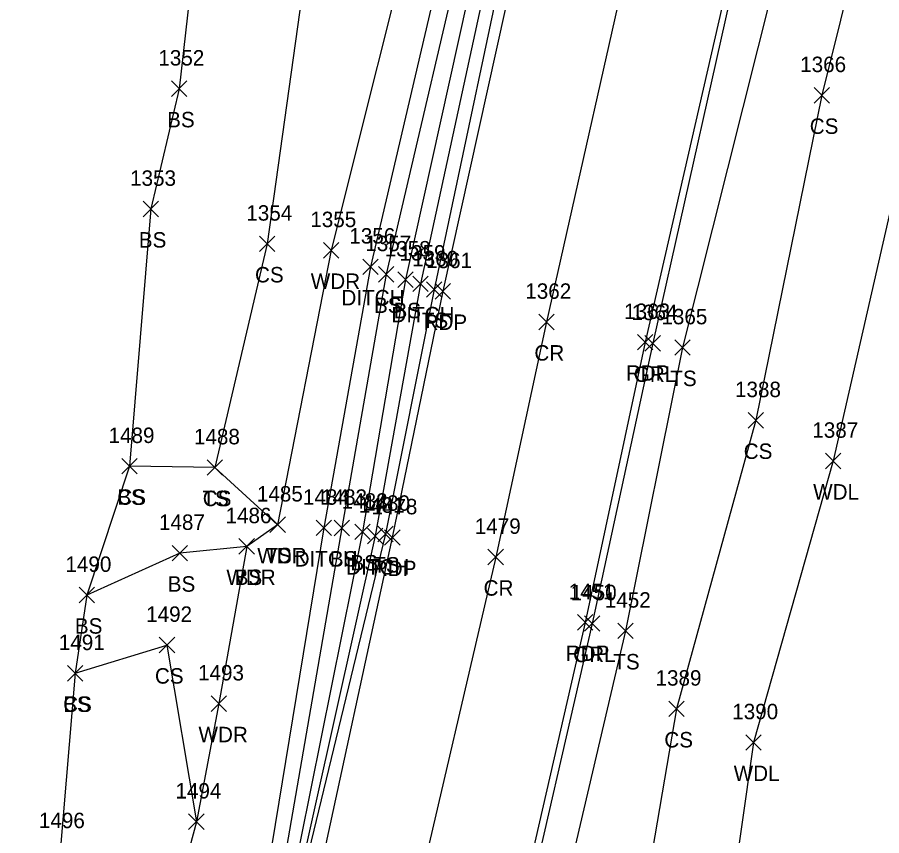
# Model space of a CAD drawing. Extents: x 1551995 to 1555700, y 777276 to 783130.
# Drawn here: x 1554796.1 to 1554908, y 777703.8 to 777809.8 of the extents above; entities that cross this region are included whole.
import ezdxf

# ---------------------------------------------------------------- set-up
doc = ezdxf.new("R2010")
doc.units = 0
for name, color, linetype in [('D_A', 7, 'Continuous'), ('D_I', 7, 'Continuous'), ('D_TIC', 7, 'Continuous'), ('DD', 7, 'Continuous'), ('L_A', 7, 'Continuous'), ('L_I', 7, 'Continuous'), ('L_TIC', 7, 'Continuous'), ('LAWA', 7, 'Continuous'), ('LELB', 7, 'Continuous'), ('P_A', 7, 'Continuous'), ('P_I', 7, 'Continuous'), ('P_TIC', 7, 'Continuous'), ('PET', 7, 'Continuous'), ('PRC', 7, 'Continuous'), ('R_A', 7, 'Continuous'), ('R_I', 7, 'Continuous'), ('R_TIC', 7, 'Continuous'), ('RGR', 7, 'Continuous')]:
    doc.layers.add(name, color=color, linetype=linetype)

msp = doc.modelspace()

# ---------------------------------------------------------------- linework, layer by layer
at = {"layer": 'D_TIC'}
for points in [[(1554840.81, 777776.5), (1554842.81, 777778.5)], [(1554842.81, 777776.5), (1554840.81, 777778.5)], [(1554847.28, 777774.3), (1554849.28, 777776.3)], [(1554849.28, 777774.3), (1554847.28, 777776.3)], [(1554834.76, 777742.69), (1554836.76, 777744.69)], [(1554836.76, 777742.69), (1554834.76, 777744.69)], [(1554841.42, 777741.65), (1554843.42, 777743.65)], [(1554843.42, 777741.65), (1554841.42, 777743.65)]]:
    msp.add_lwpolyline(points, dxfattribs=at)
at = {"layer": 'DD'}
for points in [[(1554922.06, 778109.96), (1554923.19, 778109.15), (1554925.69, 778108.05), (1554928.67, 778106.77), (1554922.03, 778089.94), (1554922.01, 778087.44), (1554918.96, 778075.67), (1554907.32, 778037.79), (1554897.01, 777996.11), (1554888.71, 777961.75), (1554879.52, 777917.82), (1554870.92, 777875.83), (1554859.53, 777827.03), (1554848.28, 777775.3), (1554842.42, 777742.65), (1554832.08, 777696.16), (1554826.68, 777674.46), (1554825.9, 777662.94)], [(1554853.39, 777826.98), (1554841.81, 777777.5), (1554835.76, 777743.69), (1554828.13, 777697.14), (1554822.33, 777678.76), (1554820.5, 777673.08), (1554821.28, 777667.69), (1554820.54, 777665.87), (1554819.99, 777658.61), (1554821.52, 777659.17), (1554812.27, 777628.19), (1554798.58, 777600.46), (1554777.91, 777552.75), (1554765.73, 777525.09), (1554749.72, 777489.17), (1554733.83, 777456.87), (1554735, 777456.04), (1554736.9, 777455.11), (1554739.85, 777453.59)]]:
    msp.add_lwpolyline(points, dxfattribs=at)
at = {"layer": 'L_TIC'}
for points in [[(1554816.04, 777799.55), (1554818.04, 777801.55)], [(1554818.04, 777799.55), (1554816.04, 777801.55)], [(1554899.26, 777798.7), (1554901.26, 777800.7)], [(1554901.26, 777798.7), (1554899.26, 777800.7)], [(1554812.37, 777783.98), (1554814.37, 777785.98)], [(1554814.37, 777783.98), (1554812.37, 777785.98)], [(1554827.42, 777779.47), (1554829.42, 777781.47)], [(1554829.42, 777779.47), (1554827.42, 777781.47)], [(1554835.72, 777778.63), (1554837.72, 777780.63)], [(1554837.72, 777778.63), (1554835.72, 777780.63)], [(1554842.83, 777775.52), (1554844.83, 777777.52)], [(1554844.83, 777775.52), (1554842.83, 777777.52)], [(1554845.36, 777774.83), (1554847.36, 777776.83)], [(1554847.36, 777774.83), (1554845.36, 777776.83)], [(1554849.05, 777773.56), (1554851.05, 777775.56)], [(1554851.05, 777773.56), (1554849.05, 777775.56)], [(1554881.23, 777766.05), (1554883.23, 777768.05)], [(1554883.23, 777766.05), (1554881.23, 777768.05)], [(1554890.71, 777756.62), (1554892.71, 777758.62)], [(1554892.71, 777756.62), (1554890.71, 777758.62)], [(1554900.73, 777751.36), (1554902.73, 777753.36)], [(1554902.73, 777751.36), (1554900.73, 777753.36)], [(1554809.59, 777750.68), (1554811.59, 777752.68)], [(1554811.59, 777750.68), (1554809.59, 777752.68)], [(1554809.59, 777750.68), (1554811.59, 777752.68)], [(1554811.59, 777750.68), (1554809.59, 777752.68)], [(1554820.65, 777750.51), (1554822.65, 777752.51)], [(1554822.65, 777750.51), (1554820.65, 777752.51)], [(1554820.65, 777750.51), (1554822.65, 777752.51)], [(1554822.65, 777750.51), (1554820.65, 777752.51)], [(1554828.79, 777743.11), (1554830.79, 777745.11)], [(1554830.79, 777743.11), (1554828.79, 777745.11)], [(1554828.79, 777743.11), (1554830.79, 777745.11)], [(1554830.79, 777743.11), (1554828.79, 777745.11)], [(1554837.11, 777742.68), (1554839.11, 777744.68)], [(1554839.11, 777742.68), (1554837.11, 777744.68)], [(1554839.77, 777742.18), (1554841.77, 777744.18)], [(1554841.77, 777742.18), (1554839.77, 777744.18)], [(1554842.76, 777741.91), (1554844.76, 777743.91)], [(1554844.76, 777741.91), (1554842.76, 777743.91)], [(1554824.78, 777740.3), (1554826.78, 777742.3)], [(1554826.78, 777740.3), (1554824.78, 777742.3)], [(1554824.78, 777740.3), (1554826.78, 777742.3)], [(1554826.78, 777740.3), (1554824.78, 777742.3)], [(1554816.12, 777739.43), (1554818.12, 777741.43)], [(1554818.12, 777739.43), (1554816.12, 777741.43)], [(1554804.09, 777734), (1554806.09, 777736)], [(1554806.09, 777734), (1554804.09, 777736)], [(1554804.09, 777734), (1554806.09, 777736)], [(1554806.09, 777734), (1554804.09, 777736)], [(1554873.85, 777729.37), (1554875.85, 777731.37)], [(1554875.85, 777729.37), (1554873.85, 777731.37)], [(1554814.46, 777727.53), (1554816.46, 777729.53)], [(1554816.46, 777727.53), (1554814.46, 777729.53)], [(1554802.57, 777723.87), (1554804.57, 777725.87)], [(1554804.57, 777723.87), (1554802.57, 777725.87)], [(1554802.57, 777723.87), (1554804.57, 777725.87)], [(1554804.57, 777723.87), (1554802.57, 777725.87)], [(1554821.18, 777719.94), (1554823.18, 777721.94)], [(1554823.18, 777719.94), (1554821.18, 777721.94)], [(1554880.43, 777719.27), (1554882.43, 777721.27)], [(1554882.43, 777719.27), (1554880.43, 777721.27)], [(1554890.43, 777714.92), (1554892.43, 777716.92)], [(1554892.43, 777714.92), (1554890.43, 777716.92)], [(1554818.26, 777704.66), (1554820.26, 777706.66)], [(1554820.26, 777704.66), (1554818.26, 777706.66)], [(1554818.26, 777704.66), (1554820.26, 777706.66)], [(1554820.26, 777704.66), (1554818.26, 777706.66)]]:
    msp.add_lwpolyline(points, dxfattribs=at)
at = {"layer": 'LAWA'}
for points in [[(1554924.17, 777845.95), (1554911.99, 777797.39), (1554901.73, 777752.36), (1554891.43, 777715.92), (1554886.53, 777681.63), (1554885.54, 777676.35), (1554886.43, 777672.72), (1554885.1, 777668.28), (1554876.24, 777640.92), (1554874.65, 777639.02), (1554865.05, 777604.93), (1554832.26, 777556.58), (1554828.6, 777545), (1554825.77, 777534.55), (1554825.26, 777531.03), (1554824.11, 777527.47), (1554817.13, 777514.36), (1554810.78, 777500.84), (1554797.7, 777469.38), (1554813.54, 777462.7)], [(1554848.67, 777827.4), (1554836.72, 777779.63), (1554829.79, 777744.11), (1554825.78, 777741.3), (1554822.18, 777720.94), (1554819.26, 777705.66), (1554810.77, 777674.16), (1554804.68, 777658.7), (1554794.95, 777639.81), (1554796.98, 777635.44), (1554794.4, 777626.38), (1554790.25, 777608.46), (1554781.8, 777582.48), (1554770.39, 777556.32), (1554759.95, 777527.2), (1554742.53, 777489.58), (1554728.19, 777462.54)]]:
    msp.add_lwpolyline(points, dxfattribs=at)
at = {"layer": 'LELB'}
for points in [[(1554956.78, 778082.85), (1554952.54, 778067.25), (1554941.7, 778025.45), (1554932.23, 777987.42), (1554924.92, 777953.42), (1554914.28, 777909.64), (1554906.04, 777867.54), (1554895.88, 777821.34), (1554882.23, 777767.05), (1554874.85, 777730.37), (1554865.16, 777689.06), (1554854.06, 777643.96), (1554841.07, 777598.56), (1554825.8, 777560.58)], [(1554954.84, 778026.93), (1554940.94, 777981.64), (1554932.87, 777954.14), (1554929.76, 777924.84), (1554918.75, 777893.91), (1554912.39, 777848.48), (1554900.26, 777799.7), (1554891.71, 777757.62), (1554881.43, 777720.27), (1554874.58, 777680.06), (1554873.83, 777672.65), (1554864.12, 777644.24), (1554854.56, 777607.14), (1554832.26, 777556.58)], [(1554818.74, 777989.99), (1554826.95, 777965.67), (1554828.21, 777938.79), (1554827.61, 777892.43), (1554825.56, 777859.47), (1554820.31, 777829.58), (1554817.04, 777800.55), (1554813.37, 777784.98), (1554810.59, 777751.68), (1554805.09, 777735), (1554803.57, 777724.87), (1554801.62, 777701.82), (1554799.08, 777679.52), (1554798, 777658.89), (1554794.95, 777639.81), (1554778.13, 777607.5), (1554759.36, 777559.57), (1554752.31, 777545.79)], [(1554828.62, 777989.99), (1554839.45, 777979.91), (1554836.31, 777967.58), (1554843.93, 777927.48), (1554845.21, 777880.49), (1554844.2, 777852.94), (1554834.62, 777824.64), (1554828.42, 777780.47), (1554821.65, 777751.51), (1554810.59, 777751.68)], [(1554870.92, 777875.83), (1554861.08, 777826.54), (1554850.05, 777774.56), (1554843.76, 777742.91), (1554832.54, 777696.52), (1554826.68, 777674.46)], [(1554855.73, 777827.33), (1554843.83, 777776.52), (1554838.11, 777743.68), (1554829.99, 777696.83), (1554823.99, 777679.3), (1554821.48, 777673.86), (1554821.86, 777673.52), (1554823.73, 777663.64), (1554822.4, 777659.03), (1554813.94, 777627.98), (1554800.18, 777599.92), (1554780.06, 777551.51), (1554767.45, 777524.55), (1554751.73, 777488.16), (1554735, 777456.04)], [(1554857.76, 777827.38), (1554846.36, 777775.83), (1554840.77, 777743.18), (1554831.41, 777696.67), (1554825.48, 777677.69), (1554824.51, 777673.63), (1554823.78, 777673.32), (1554824.92, 777663.42), (1554823.59, 777658.72), (1554814.97, 777627.54), (1554801.99, 777599.47), (1554782.65, 777550.32), (1554769.22, 777523.47), (1554754.18, 777487.46), (1554736.9, 777455.11)], [(1554829.79, 777744.11), (1554821.65, 777751.51)], [(1554825.78, 777741.3), (1554817.12, 777740.43), (1554805.09, 777735)], [(1554803.57, 777724.87), (1554815.46, 777728.53), (1554819.26, 777705.66)]]:
    msp.add_lwpolyline(points, dxfattribs=at)
at = {"layer": 'P_TIC'}
for points in [[(1554850.19, 777773.32), (1554852.19, 777775.32)], [(1554852.19, 777773.32), (1554850.19, 777775.32)], [(1554863.6, 777769.35), (1554865.6, 777771.35)], [(1554865.6, 777769.35), (1554863.6, 777771.35)], [(1554876.4, 777766.74), (1554878.4, 777768.74)], [(1554878.4, 777766.74), (1554876.4, 777768.74)], [(1554843.64, 777741.45), (1554845.64, 777743.45)], [(1554845.64, 777741.45), (1554843.64, 777743.45)], [(1554857.03, 777738.92), (1554859.03, 777740.92)], [(1554859.03, 777738.92), (1554857.03, 777740.92)], [(1554868.61, 777730.46), (1554870.61, 777732.46)], [(1554870.61, 777730.46), (1554868.61, 777732.46)]]:
    msp.add_lwpolyline(points, dxfattribs=at)
at = {"layer": 'PET'}
for points in [[(1554862.74, 777826.66), (1554851.19, 777774.32), (1554844.64, 777742.45), (1554834.58, 777696.01), (1554825.9, 777662.94), (1554824.47, 777658.25), (1554815.91, 777627.5), (1554805.87, 777597.98), (1554786.84, 777548.46), (1554774.55, 777520.74), (1554758.12, 777485.1), (1554742.1, 777452.42), (1554722.77, 777413.11), (1554709.98, 777388.33), (1554692.97, 777354.45), (1554662.63, 777294.3)], [(1554889.9, 777822.39), (1554877.4, 777767.74), (1554869.61, 777731.46), (1554860.02, 777689.61), (1554848.79, 777645.37), (1554834.77, 777600.99), (1554821.88, 777564.77), (1554812, 777537.71), (1554799.6, 777509.17), (1554784.62, 777476.27), (1554767.28, 777440.72), (1554755.97, 777417.1), (1554737.76, 777381.53), (1554717.46, 777342.52), (1554685.83, 777281.18)]]:
    msp.add_lwpolyline(points, dxfattribs=at)
at = {"layer": 'PRC'}
msp.add_lwpolyline([(1554876.72, 777824.26), (1554864.6, 777770.35), (1554858.03, 777739.92), (1554847.21, 777693.38), (1554836.59, 777653.01), (1554828.61, 777623.61), (1554818.04, 777593.07), (1554799.63, 777543.85), (1554787.19, 777515.25), (1554771.79, 777480.71), (1554754.78, 777446.13), (1554727.16, 777390.73), (1554704.95, 777347.63), (1554675, 777287.76)], dxfattribs=at)
at = {"layer": 'R_TIC'}
for points in [[(1554877.36, 777766.59), (1554879.36, 777768.59)], [(1554879.36, 777766.59), (1554877.36, 777768.59)], [(1554869.52, 777730.32), (1554871.52, 777732.32)], [(1554871.52, 777730.32), (1554869.52, 777732.32)]]:
    msp.add_lwpolyline(points, dxfattribs=at)
at = {"layer": 'RGR'}
msp.add_lwpolyline([(1555039.56, 778268.3), (1555013.62, 778223), (1554996.63, 778189.88), (1554979.88, 778154.08), (1554968.24, 778124.65), (1554958.2, 778096.32), (1554950.97, 778072.94), (1554937.27, 778027.95), (1554927.65, 777988.1), (1554919.66, 777954.37), (1554909.72, 777910.11), (1554900.5, 777868.18), (1554890.69, 777822.54), (1554878.36, 777767.59), (1554870.52, 777731.32), (1554860.9, 777689.38), (1554849.55, 777645.14), (1554835.81, 777600.33), (1554822.79, 777564.15), (1554817.07, 777548.72), (1554816.7, 777536.06)], dxfattribs=at)

# ---------------------------------------------------------------- texts
at = {"layer": 'D_A'}
for p in [(1554838.05, 777772.5), (1554844.52, 777770.3), (1554831.99, 777738.69), (1554838.66, 777737.65)]:
    msp.add_text('DITCH', height=2, dxfattribs=at).set_placement(p)
at = {"layer": 'D_I'}
for s, p in [('1356', (1554839.07, 777780.5)), ('1359', (1554845.58, 777778.3)), ('1484', (1554833.06, 777746.69)), ('1481', (1554840.3, 777745.65))]:
    msp.add_text(s, height=2, dxfattribs=at).set_placement(p)
at = {"layer": 'L_A'}
for s, p in [('BS', (1554815.48, 777795.55)), ('CS', (1554898.7, 777794.7)), ('BS', (1554811.81, 777779.98)), ('CS', (1554826.86, 777775.47)), ('WDR', (1554834.08, 777774.63)), ('BS', (1554842.27, 777771.52)), ('BS', (1554844.8, 777770.83)), ('TS', (1554848.46, 777769.56)), ('TS', (1554880.64, 777762.05)), ('CS', (1554890.15, 777752.62)), ('WDL', (1554899.14, 777747.36)), ('CS', (1554809.03, 777746.68)), ('BS', (1554809.03, 777746.68)), ('TS', (1554820.05, 777746.51)), ('CS', (1554820.09, 777746.51)), ('WDR', (1554827.15, 777739.11)), ('TS', (1554828.2, 777739.11)), ('BS', (1554836.55, 777738.68)), ('BS', (1554839.21, 777738.18)), ('TS', (1554842.17, 777737.91)), ('WDR', (1554823.15, 777736.3)), ('BS', (1554824.22, 777736.3)), ('BS', (1554815.56, 777735.43)), ('BS', (1554803.53, 777730)), ('BS', (1554803.53, 777730)), ('TS', (1554873.26, 777725.37)), ('CS', (1554813.9, 777723.53)), ('CS', (1554802.01, 777719.87)), ('BS', (1554802.01, 777719.87)), ('WDR', (1554819.54, 777715.94)), ('CS', (1554879.87, 777715.27)), ('WDL', (1554888.85, 777710.92))]:
    msp.add_text(s, height=2, dxfattribs=at).set_placement(p)
at = {"layer": 'L_I'}
for s, p in [('1352', (1554814.34, 777803.55)), ('1366', (1554897.46, 777802.7)), ('1353', (1554810.68, 777787.98)), ('1354', (1554825.73, 777783.47)), ('1355', (1554834.02, 777782.63)), ('1357', (1554841.14, 777779.52)), ('1358', (1554843.66, 777778.83)), ('1360', (1554847.22, 777777.56)), ('1365', (1554879.49, 777770.05)), ('1388', (1554889.02, 777760.62)), ('1387', (1554899.03, 777755.36)), ('1489', (1554807.89, 777754.68)), ('1489', (1554807.89, 777754.68)), ('1488', (1554818.95, 777754.51)), ('1488', (1554818.95, 777754.51)), ('1485', (1554827.1, 777747.11)), ('1485', (1554827.1, 777747.11)), ('1483', (1554835.42, 777746.68)), ('1482', (1554838.08, 777746.18)), ('1480', (1554840.98, 777745.91)), ('1486', (1554823.04, 777744.3)), ('1486', (1554823.04, 777744.3)), ('1487', (1554814.42, 777743.43)), ('1490', (1554802.31, 777738)), ('1490', (1554802.31, 777738)), ('1452', (1554872.16, 777733.37)), ('1492', (1554812.76, 777731.53)), ('1491', (1554801.45, 777727.87)), ('1491', (1554801.45, 777727.87)), ('1493', (1554819.48, 777723.94)), ('1389', (1554878.73, 777723.27)), ('1390', (1554888.66, 777718.92)), ('1494', (1554816.56, 777708.66)), ('1494', (1554816.56, 777708.66)), ('1496', (1554798.87, 777704.82))]:
    msp.add_text(s, height=2, dxfattribs=at).set_placement(p)
at = {"layer": 'P_A'}
for s, p in [('RDP', (1554848.68, 777769.32)), ('CR', (1554863.04, 777765.35)), ('RDP', (1554874.89, 777762.74)), ('RDP', (1554842.12, 777737.45)), ('CR', (1554856.46, 777734.92)), ('RDP', (1554867.1, 777726.46))]:
    msp.add_text(s, height=2, dxfattribs=at).set_placement(p)
at = {"layer": 'P_I'}
for s, p in [('1361', (1554849.02, 777777.32)), ('1362', (1554861.86, 777773.35)), ('1363', (1554874.66, 777770.74)), ('1478', (1554841.94, 777745.45)), ('1479', (1554855.32, 777742.92)), ('1451', (1554867.48, 777734.46))]:
    msp.add_text(s, height=2, dxfattribs=at).set_placement(p)
at = {"layer": 'R_A'}
for p in [(1554875.91, 777762.59), (1554868.06, 777726.32)]:
    msp.add_text('GRL', height=2, dxfattribs=at).set_placement(p)
at = {"layer": 'R_I'}
for s, p in [('1364', (1554875.62, 777770.59)), ('1450', (1554867.74, 777734.32))]:
    msp.add_text(s, height=2, dxfattribs=at).set_placement(p)

doc.saveas('drawing.dxf')
